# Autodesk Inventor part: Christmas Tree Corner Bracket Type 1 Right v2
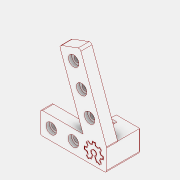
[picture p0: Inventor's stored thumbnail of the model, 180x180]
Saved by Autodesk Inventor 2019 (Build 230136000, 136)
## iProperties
Created: 2025-12
Part Number: Christmas Tree Corner Bracket Type 1 Right v2
Material: ABS Plastic
Document SubType Name: Modeling
Designer: sab
Density: 1.06 g/cm^3
Appearance: Red
Mass: 24.4978 g
Surface Area: 88.7218 cm^2
Volume: 23.1111 cm^3
Author: sab
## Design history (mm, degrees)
node "Blocks"
  sketch "Block1"
    geometry: L1 (0, 0.5)-(342.02, 940.193); L2 (0, -4.92)-(0, 0); L3 (0, -19.5)-(684.04, -19.5); L4 (21.284, 0.5)-(342.02, 881.717); L5 (0, 0.5)-(684.04, 0.5); L6 (662.757, 0.5)-(342.02, 881.717); L7 (684.04, 0.5)-(342.02, 940.193); L8 (684.04, -4.92)-(684.04, 0); L9 (0, 0.5)-(0, 0); L10 (684.04, 0.5)-(684.04, 0); 1 further point
    constraints: 20 end point
  sketch "Block1_1"
    geometry: L1 (-5.09, 2.943)-(-3.464, 3.257); L2 (-3.464, 3.257)-(-2.886, 4.652); L3 (-2.886, 4.652)-(-3.839, 6.061); L4 (-3.839, 6.061)-(-2.636, 7.264); L5 (-2.636, 7.264)-(-1.238, 6.318); L6 (-1.238, 6.318)-(0.22, 6.922); L7 (0.22, 6.922)-(0.531, 8.532); L8 (0.531, 8.532)-(2.267, 8.532); L9 (2.267, 8.532)-(2.588, 6.869); L10 (2.588, 6.869)-(4.046, 6.265); L11 (4.046, 6.265)-(5.403, 7.184); L12 (5.403, 7.184)-(6.631, 5.956); L13 (6.631, 5.956)-(5.682, 4.554); L14 (5.682, 4.554)-(6.286, 3.096); L15 (6.286, 3.096)-(7.895, 2.785); L16 (7.895, 2.785)-(7.895, 1.05); L17 (7.895, 1.05)-(6.232, 0.729); L18 (6.232, 0.729)-(5.627, -0.731); L19 (5.627, -0.731)-(6.541, -2.081); L20 (6.541, -2.081)-(5.344, -3.279); L21 (5.344, -3.279)-(3.887, -2.293); L22 (3.887, -2.293)-(3.329, -2.524); L23 (3.329, -2.524)-(2.197, 0.247); L24 (0.657, 0.303)-(-0.496, -2.521); L25 (-0.496, -2.521)-(-1.178, -2.239); L26 (-1.178, -2.239)-(-2.536, -3.157); L27 (-2.536, -3.157)-(-3.766, -1.927); L28 (-3.766, -1.927)-(-2.82, -0.529); L29 (-2.82, -0.529)-(-3.42, 0.919); L30 (-3.42, 0.919)-(-5.09, 1.242); L31 (-5.09, 1.242)-(-5.09, 2.943); A1 r 0.085 centre (-3.45, 3.333) between (-3.434, 3.25) and (-3.371, 3.301); A2 r 0.085 centre (-2.899, 4.663) between (-2.82, 4.63) and (-2.828, 4.711); A3 r 0.085 centre (-3.663, 6.098) between (-3.724, 6.158) and (-3.734, 6.05); A4 r 0.085 centre (-2.519, 7.242) between (-2.471, 7.312) and (-2.58, 7.302); A5 r 0.085 centre (-1.085, 6.477) between (-1.132, 6.407) and (-1.052, 6.398); A6 r 0.085 centre (0.245, 7.028) between (0.278, 6.949) and (0.329, 7.012); A7 r 0.085 centre (0.719, 8.583) between (0.719, 8.668) and (0.635, 8.599); A8 r 0.085 centre (2.337, 8.583) between (2.421, 8.599) and (2.337, 8.668); A9 r 0.085 centre (2.811, 7.028) between (2.727, 7.012) and (2.778, 6.949); A10 r 0.085 centre (4.14, 6.477) between (4.108, 6.398) and (4.188, 6.407); A11 r 0.085 centre (5.575, 7.242) between (5.636, 7.302) and (5.527, 7.312); A12 r 0.085 centre (6.719, 6.098) between (6.79, 6.05) and (6.78, 6.158); A13 r 0.085 centre (5.955, 4.663) between (5.884, 4.711) and (5.876, 4.63); A14 r 0.085 centre (6.506, 3.333) between (6.427, 3.301) and (6.489, 3.25); A15 r 0.085 centre (8.06, 2.859) between (8.146, 2.859) and (8.077, 2.943); A16 r 0.085 centre (8.06, 1.242) between (8.077, 1.158) and (8.146, 1.242); A17 r 0.085 centre (6.506, 0.768) between (6.489, 0.851) and (6.427, 0.8); A18 r 0.085 centre (5.955, -0.562) between (5.876, -0.529) and (5.884, -0.61); A19 r 0.085 centre (6.719, -1.997) between (6.78, -2.057) and (6.79, -1.949); A20 r 0.085 centre (5.575, -3.141) between (5.527, -3.212) and (5.636, -3.201); A21 r 0.085 centre (4.14, -2.376) between (4.188, -2.306) and (4.108, -2.297); A22 r 0.085 centre (3.466, -2.471) between (3.387, -2.503) and (3.499, -2.55); A23 r 0.085 centre (2.345, 0.274) between (2.31, 0.352) and (2.266, 0.242); A24 r 1.87 centre (1.489, 1.977) between (2.197, 0.247) and (0.657, 0.303); A25 r 0.085 centre (0.71, 0.274) between (0.79, 0.242) and (0.746, 0.352); A26 r 0.085 centre (-0.41, -2.471) between (-0.443, -2.55) and (-0.331, -2.503); A27 r 0.085 centre (-1.085, -2.376) between (-1.052, -2.297) and (-1.132, -2.306); A28 r 0.085 centre (-2.519, -3.141) between (-2.58, -3.201) and (-2.471, -3.212); A29 r 0.085 centre (-3.663, -1.997) between (-3.734, -1.949) and (-3.724, -2.057); A30 r 0.085 centre (-2.899, -0.562) between (-2.828, -0.61) and (-2.82, -0.529); A31 r 0.085 centre (-3.45, 0.768) between (-3.371, 0.8) and (-3.434, 0.851); A32 r 0.085 centre (-5.005, 1.242) between (-5.09, 1.242) and (-5.021, 1.158); A33 r 0.085 centre (-5.005, 2.859) between (-5.021, 2.943) and (-5.09, 2.859); 1 further point
    constraints: 66 point on circle, 62 end point, 33 centre point
  sketch "Block1_2"
    geometry: L1 (-0.89, -10)-(-0.68, -10.21); L2 (-0.89, -10)-(-0.68, -9.79); L3 (-0.68, -9.79)-(-0.68, -7.161); L4 (-0.68, -7.161)-(1.981, -4.5); L5 (1.981, -4.5)-(3.62, -4.5); L6 (3.62, -4.5)-(3.62, -6.875); L7 (3.62, -6.875)-(3.965, -6.875); L8 (3.965, -6.875)-(5.42, -5.42); L9 (5.42, -5.42)-(5.42, -0.5); L10 (4.92, 0)-(0, 0); L11 (-1.455, -1.455)-(0, 0); L12 (-1.455, -1.8)-(-1.455, -1.455); L13 (0.92, -1.8)-(-1.455, -1.8); L14 (0.92, -3.439)-(0.92, -1.8); L15 (-1.741, -6.1)-(0.92, -3.439); L16 (-4.37, -6.1)-(-1.741, -6.1); L17 (-4.58, -6.31)-(-4.37, -6.1); L18 (-4.58, -6.31)-(-4.79, -6.1); L19 (-4.79, -6.1)-(-7.419, -6.1); L20 (-7.419, -6.1)-(-10.08, -3.439); L21 (-10.08, -3.439)-(-10.08, -1.8); L22 (-10.08, -1.8)-(-7.705, -1.8); L23 (-7.705, -1.8)-(-7.705, -1.455); L24 (-7.705, -1.455)-(-9.16, 0); L25 (-9.16, 0)-(-14.08, 0); L26 (-14.58, -5.42)-(-14.58, -0.5); L27 (-13.125, -6.875)-(-14.58, -5.42); L28 (-12.78, -6.875)-(-13.125, -6.875); L29 (-12.78, -4.5)-(-12.78, -6.875); L30 (-11.141, -4.5)-(-12.78, -4.5); L31 (-8.48, -7.161)-(-11.141, -4.5); L32 (-8.48, -9.79)-(-8.48, -7.161); L33 (-8.27, -10)-(-8.48, -9.79); L34 (-8.27, -10)-(-8.48, -10.21); L35 (-8.48, -10.21)-(-8.48, -12.839); L36 (-8.48, -12.839)-(-11.141, -15.5); L37 (-11.141, -15.5)-(-12.78, -15.5); L38 (-12.78, -15.5)-(-12.78, -13.125); L39 (-12.78, -13.125)-(-13.125, -13.125); L40 (-13.125, -13.125)-(-14.58, -14.58); L41 (-14.58, -19.5)-(-14.58, -14.58); L42 (-9.16, -20)-(-14.08, -20); L43 (-7.705, -18.545)-(-9.16, -20); L44 (-7.705, -18.2)-(-7.705, -18.545); L45 (-10.08, -18.2)-(-7.705, -18.2); L46 (-10.08, -16.561)-(-10.08, -18.2); L47 (-7.419, -13.9)-(-10.08, -16.561); L48 (-4.79, -13.9)-(-7.419, -13.9); L49 (-4.58, -13.69)-(-4.79, -13.9); L50 (-4.58, -13.69)-(-4.37, -13.9); L51 (-4.37, -13.9)-(-1.741, -13.9); L52 (-1.741, -13.9)-(0.92, -16.561); L53 (0.92, -16.561)-(0.92, -18.2); L54 (0.92, -18.2)-(-1.455, -18.2); L55 (-1.455, -18.2)-(-1.455, -18.545); L56 (-1.455, -18.545)-(0, -20); L57 (4.92, -20)-(0, -20); L58 (5.42, -19.5)-(5.42, -14.58); L59 (3.965, -13.125)-(5.42, -14.58); L60 (3.62, -13.125)-(3.965, -13.125); L61 (3.62, -15.5)-(3.62, -13.125); L62 (1.981, -15.5)-(3.62, -15.5); L63 (-0.68, -12.839)-(1.981, -15.5); L64 (-0.68, -10.21)-(-0.68, -12.839)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; C1 r 2.1 at (-4.58, -10); A1 r 0.5 centre (4.92, -0.5) between (5.42, -0.5) and (4.92, 0); A2 r 0.5 centre (-14.08, -0.5) between (-14.08, 0) and (-14.58, -0.5); A3 r 0.5 centre (-14.08, -19.5) between (-14.58, -19.5) and (-14.08, -20); A4 r 0.5 centre (4.92, -19.5) between (4.92, -20) and (5.42, -19.5); A5 r 0.75 centre (4.92, -0.5) between (5.67, -0.5) and (4.92, 0.25); A6 r 0.75 centre (4.92, -19.5) between (4.92, -20.25) and (5.67, -19.5); A7 r 0.75 centre (-14.08, -19.5) between (-14.83, -19.5) and (-14.08, -20.25); A8 r 0.75 centre (-14.08, -0.5) between (-14.08, 0.25) and (-14.83, -0.5); 2 further points
    constraints: 256 end point, 16 point on circle, 9 centre point, 67 other
    dimensions: "d33" = 0.25 distance between parallel lines of L24 L65
sketch "Sketch1"
  geometry: L1 (0, 0)-(21.284, 0); L2 (60, 0)-(60, -20); L3 (60, -20)-(0, -20); L4 (0, -20)-(0, 0); L5 (0, 0)-(23.941, 65.778); L6 (23.941, 65.778)-(42.735, 58.938); L7 (42.735, 58.938)-(21.284, 0); L8 (18.794, -6.84)-(0, 0); L9 (21.284, 0)-(18.794, -6.84); L10 (21.284, 0)-(60, 0); L11 (0, -10)-(60, -10); L12 (33.338, 62.358)-(8.133, -2.96); 8 further points
  constraints: 24 end point, 6 parallel, 6 point on line, 4 midpoint, 3 horizontal, 3 perpendicular, 1 coincident, 6 other
  dimensions: "d0" = 60 distance of L2.end L3.end; "d1" = 70 distance of L5.start L5.end; "d2" = 30 distance from line of point (30, -10) L4 (= 0.5 x d0); "d3" = 20 distance of point (30, -10) point (10, -10); "d4" = 20 distance of point (30, -10) point (50, -10) (= d3); "d5" = 30 distance from line of point (22.536, 34.365) L6 (= d2); "d6" = 10 distance from line of L6 point (29.738, 53.027); "d7" = 20 distance from line of L8 point (15.334, 15.702); "d19" = 21.28356 distance from line of L1.end L4
  node "Block1:1" dims "d0" = 60, "d1" = 70, "d2" = 30 (= 0.5 x d0), "d3" = 20, "d4" = 20 (= d3), "d5" = 30 (= d2), "d6" = 10, "d7" = 20, "d19" = 21.28356
  node "Block2:1" dims "d0" = 60, "d1" = 70, "d2" = 30 (= 0.5 x d0), "d3" = 20, "d4" = 20 (= d3), "d5" = 30 (= d2), "d6" = 10, "d7" = 20, "d19" = 21.28356
extrude "Extrusion1" new body sketch "Sketch1" distance "d8" = 10; taper "d9" = 0 deg
hole "Hole1" sketch "Sketch1" diameter "d10" = 5.4; stored, may be unused: countersink angle "d14" = 90 deg, drill point angle "d16" = 118 deg; dims "d11" = 12.7, "d12" = 9.5, "d13" = 3, "d15" = 8
emboss "Emboss1" sketch "Sketch1" dims "d0" = 60, "d1" = 70, "d2" = 30 (= 0.5 x d0), "d3" = 20, "d4" = 20 (= d3), "d5" = 30 (= d2), "d6" = 10, "d7" = 20, "d17" = 0.3, "d18" = 0, "d19" = 21.28356
fillet "Fillet1" dims "d21" = 2
sketch "Sketch2"
  geometry: L1 (-42.051, 57.059)-(-21.284, 0) reference; L2 (-21.284, 0)-(-58, 0) reference; L3 (-60, -2)-(-60, -18) reference; L4 (-58, -20)-(-2, -20) reference; L5 (0, -18)-(0, -0.353) reference; L6 (-0.121, 0.331)-(-23.257, 63.899) reference; L7 (-25.821, 65.094)-(-40.856, 59.622) reference; L8 (-21.284, 0)-(0, 0); L9 (0, 0)-(0, -20); L10 (0, -20)-(-21.284, -20); L11 (-21.284, -20)-(-21.284, 0); C1 r 2.7 at (-29.738, 53.027) reference; C2 r 2.7 at (-50, -10) reference; C3 r 2.7 at (-30, -10) reference; C4 r 2.7 at (-22.536, 34.365) reference; C5 r 2.7 at (-15.334, 15.702) reference; A1 r 2 centre (-40.172, 57.743) between (-40.856, 59.622) and (-42.051, 57.059) reference; A2 r 2 centre (-58, -2) between (-58, 0) and (-60, -2) reference; A3 r 2 centre (-58, -18) between (-60, -18) and (-58, -20) reference; A4 r 2 centre (-2, -18) between (-2, -20) and (0, -18) reference; A5 r 2 centre (-2, -0.353) between (0, -0.353) and (-0.121, 0.331) reference; A6 r 2 centre (-25.137, 63.215) between (-23.257, 63.899) and (-25.821, 65.094) reference; 1 further point
  constraints: 8 end point, 2 parallel, 1 horizontal, 1 perpendicular
extrude "Extrusion2" join sketch "Sketch2" distance "d22" = 20; taper "d23" = 0 deg
fillet "Fillet2" dims "d24" = 2
sketch "Sketch3"
  geometry: L1 (0, 0)-(-21.284, 0) reference; L2 (-21.284, 0)-(-21.284, -20) reference
emboss "Emboss2" sketch "Sketch3" dims "d0" = 60, "d1" = 70, "d2" = 30 (= 0.5 x d0), "d3" = 20, "d4" = 20 (= d3), "d5" = 30 (= d2), "d6" = 10, "d7" = 20, "d19" = 21.28356, "d25" = 0.3, "d26" = 0
sketch "Sketch4"
  geometry: L1 (0, 20)-(0, 18) reference; L2 (-10, 2)-(20, 2) reference; L3 (0, 18)-(18, 18); L4 (18, 18)-(18, 2); L5 (18, 2)-(0, 2); L6 (0, 2)-(0, 18); 1 further point
  constraints: 8 end point, 2 parallel, 1 horizontal, 1 perpendicular, 1 point on line
  dimensions: "d29" = 18 distance of L4.end L5.end
extrude "Extrusion3" cut sketch "Sketch4" distance "d30" = 18; taper "d31" = 0 deg
mirror "Mirror1"
fillet "Fillet3" dims "d32" = 0.5
sketch "Sketch5"
  geometry: L1 (20.784, 20)-(0, 20) reference; L2 (0, 0)-(0, 20) reference; L3 (0, 0)-(21.252, 0) reference; L4 (21.284, 0)-(21.252, 0) reference; L5 (21.284, 0)-(21.284, 19.5) reference; L6 (0, 18)-(0, 0) reference; L7 (0, 14.748)-(6, 14.748); L8 (6, 14.748)-(6, 4.748); L9 (6, 4.748)-(0, 4.748); L10 (0, 4.748)-(0, 14.748); L11 (6, 14.748)-(0, 4.748); L12 (6, 4.748)-(0, 14.748); L13 (6.936, 9.75)-(-1.744, 9.75); A1 r 0.5 centre (20.784, 19.5) between (21.284, 19.5) and (20.784, 20) reference; 2 further points
  constraints: 14 end point, 2 parallel, 2 perpendicular, 1 horizontal, 1 midpoint, 1 other
  dimensions: "d34" = 6 distance of L8.end L9.end; "d38" = 10 distance between parallel lines of L9 L7
extrude "Extrusion4" cut sketch "Sketch5" distance "d35" = 10; taper "d36" = 0 deg
fillet "Fillet4" dims "d37" = 0.5
body "Solid1"
node "Projected Loop1"
sketch "Block2"
  geometry: L1 (-78.347, -9.505)-(-78.347, -12.199); L2 (-78.347, -12.199)-(-76.112, -12.63); L3 (-76.112, -12.63)-(-75.466, -14.191); L4 (-75.466, -14.191)-(-76.732, -16.063); L5 (-76.732, -16.063)-(-74.792, -18.002); L6 (-74.792, -18.002)-(-72.972, -16.771); L7 (-72.972, -16.771)-(-71.963, -17.189); L8 (-71.963, -17.189)-(-70.249, -12.99); L9 (-69.071, -13.039)-(-67.375, -17.193); L10 (-67.375, -17.193)-(-66.525, -16.84); L11 (-66.525, -16.84)-(-64.577, -18.158); L12 (-64.577, -18.158)-(-62.68, -16.261); L13 (-62.68, -16.261)-(-63.905, -14.45); L14 (-63.905, -14.45)-(-63.253, -12.876); L15 (-63.253, -12.876)-(-61.026, -12.446); L16 (-61.026, -12.446)-(-61.026, -9.709); L17 (-61.026, -9.709)-(-63.183, -9.293); L18 (-63.183, -9.293)-(-63.835, -7.72); L19 (-63.835, -7.72)-(-62.565, -5.843); L20 (-62.565, -5.843)-(-64.501, -3.907); L21 (-64.501, -3.907)-(-66.32, -5.138); L22 (-66.32, -5.138)-(-67.893, -4.486); L23 (-67.893, -4.486)-(-68.322, -2.261); L24 (-68.322, -2.261)-(-71.06, -2.261); L25 (-71.06, -2.261)-(-71.477, -4.418); L26 (-71.477, -4.418)-(-73.049, -5.069); L27 (-73.049, -5.069)-(-74.921, -3.803); L28 (-74.921, -3.803)-(-76.826, -5.708); L29 (-76.826, -5.708)-(-75.55, -7.593); L30 (-75.55, -7.593)-(-76.168, -9.085); L31 (-76.168, -9.085)-(-78.347, -9.505); L32 (-75.73, -9.622)-(-77.736, -10.009); L33 (-77.736, -10.009)-(-77.736, -11.695); L34 (-77.736, -11.695)-(-75.674, -12.093); L35 (-75.674, -12.093)-(-74.776, -14.261); L36 (-74.776, -14.261)-(-75.943, -15.987); L37 (-75.943, -15.987)-(-74.717, -17.214); L38 (-74.717, -17.214)-(-73.042, -16.08); L39 (-73.042, -16.08)-(-72.297, -16.389); L40 (-72.297, -16.389)-(-71.03, -13.288); L41 (-68.273, -13.378)-(-67.041, -16.393); L42 (-67.041, -16.393)-(-66.455, -16.15); L43 (-66.455, -16.15)-(-64.653, -17.369); L44 (-64.653, -17.369)-(-63.468, -16.185); L45 (-63.468, -16.185)-(-64.595, -14.52); L46 (-64.595, -14.52)-(-63.691, -12.338); L47 (-63.691, -12.338)-(-61.637, -11.942); L48 (-61.637, -11.942)-(-61.637, -10.213); L49 (-61.637, -10.213)-(-63.622, -9.83); L50 (-63.622, -9.83)-(-64.525, -7.65); L51 (-64.525, -7.65)-(-63.353, -5.918); L52 (-63.353, -5.918)-(-64.576, -4.695); L53 (-64.576, -4.695)-(-66.25, -5.828); L54 (-66.25, -5.828)-(-68.43, -4.925); L55 (-68.43, -4.925)-(-68.826, -2.872); L56 (-68.826, -2.872)-(-70.556, -2.872); L57 (-70.556, -2.872)-(-70.939, -4.856); L58 (-70.939, -4.856)-(-73.119, -5.759); L59 (-73.119, -5.759)-(-74.845, -4.591); L60 (-74.845, -4.591)-(-76.037, -5.783); L61 (-76.037, -5.783)-(-74.86, -7.523); L62 (-74.86, -7.523)-(-75.73, -9.622); L63 (-78.042, -11.948)-(-78.042, -9.757); L64 (-78.042, -9.757)-(-75.95, -9.353)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; A1 r 2.101 centre (-69.575, -11) between (-69.071, -13.039) and (-70.249, -12.99); A2 r 2.711 centre (-69.575, -11) between (-68.273, -13.378) and (-71.03, -13.288); A3 r 2.406 centre (-69.575, -11) between (-68.665, -13.227) and (-70.645, -13.154); 1 further point
  constraints: 186 end point, 6 point on circle, 3 centre point, 62 other
  dimensions: "d27" = 0.305 distance between parallel lines of L63 L1; "d28" = 0.3058 distance between parallel lines of L64 L32
node "Projected Loop2"
node "Block1_1:2"
node "Block1_2:1"
